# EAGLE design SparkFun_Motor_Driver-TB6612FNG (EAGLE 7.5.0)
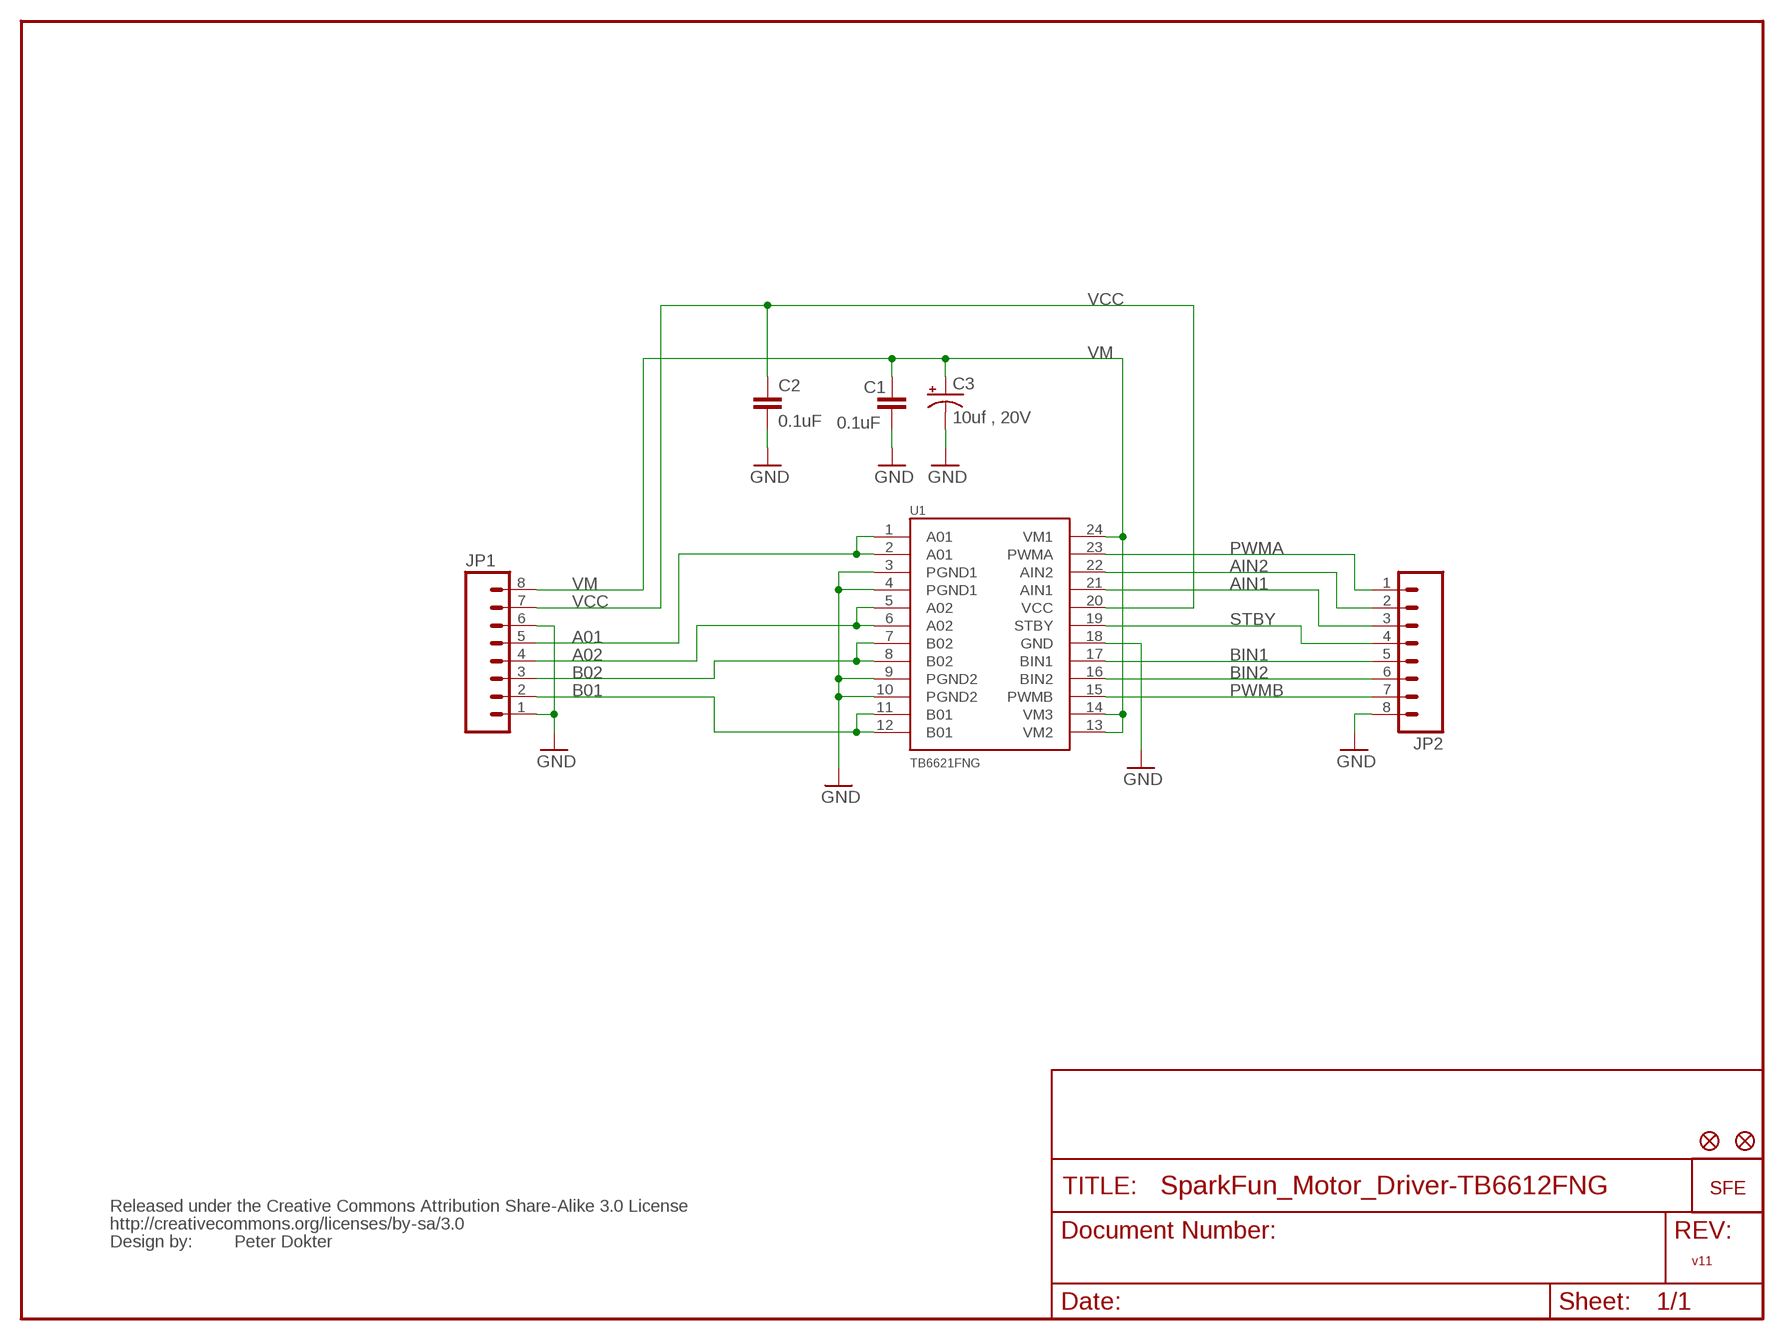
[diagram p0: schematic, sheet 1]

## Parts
C1  0.1uF  CAP0402-CAP  [0402-CAP]
C2  0.1uF  CAP0402-CAP  [0402-CAP]
C3  10uf , 20V  CAP_POL3528  [EIA3528]
JP1  M08LONGPADS  [1X08_LONGPADS]
JP2  M08LONGPADS  [1X08_LONGPADS]
JP4  LOGO-SFESK  [SFE-LOGO-FLAME]
JP5  FIDUCIAL1X2  [FIDUCIAL-1X2]
JP6  FIDUCIAL1X2  [FIDUCIAL-1X2]
U1  TB6621FNG  [SSOP24]
U$1  CREATIVE_COMMONS  [CREATIVE_COMMONS]

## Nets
A01: JP1.5 U1.1(A01) U1.2(A01)
A02: JP1.4 U1.5(A02) U1.6(A02)
AIN1: JP2.3 U1.21(AIN1)
AIN2: JP2.2 U1.22(AIN2)
B01: JP1.2 U1.11(B01) U1.12(B01)
B02: JP1.3 U1.7(B02) U1.8(B02)
BIN1: JP2.5 U1.17(BIN1)
BIN2: JP2.6 U1.16(BIN2)
GND: C1.2 C2.2 C3.C(-) JP1.1 JP1.6 JP2.8 U1.3(PGND1) U1.4(PGND1) U1.9(PGND2) U1.10(PGND2) U1.18(GND)
PWMA: JP2.1 U1.23(PWMA)
PWMB: JP2.7 U1.15(PWMB)
STBY: JP2.4 U1.19(STBY)
VCC: C2.1 JP1.7 U1.20(VCC)
VM: C1.1 C3.A(+) JP1.8 U1.13(VM2) U1.14(VM3) U1.24(VM1)

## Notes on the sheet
- Peter Dokter
- v11

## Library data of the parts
C1 C2 = SparkFun:CAP: Capacitor
C3 = SparkFun:CAP_POL: Capacitor Polarized
JP1 JP2 = SparkFun:M08: Header 8 Standard 8-pin 0.1" header. Use with straight break away headers (SKU : PRT-00116), right angle break away headers (PRT-00553), swiss pins (PRT-00743), machine pins (PRT-00117), and female headers (PRT-00115).
JP4 = SparkFun:LOGO-SFE: Spark Fun Electronics PCB Logo
JP5 JP6 = SparkFun:FIDUCIAL: Fiducial Alignment Points
U1 = SparkFun:TB6621FNG: Toshiba 1A motor driver
U$1 = SparkFun:CREATIVE_COMMONS

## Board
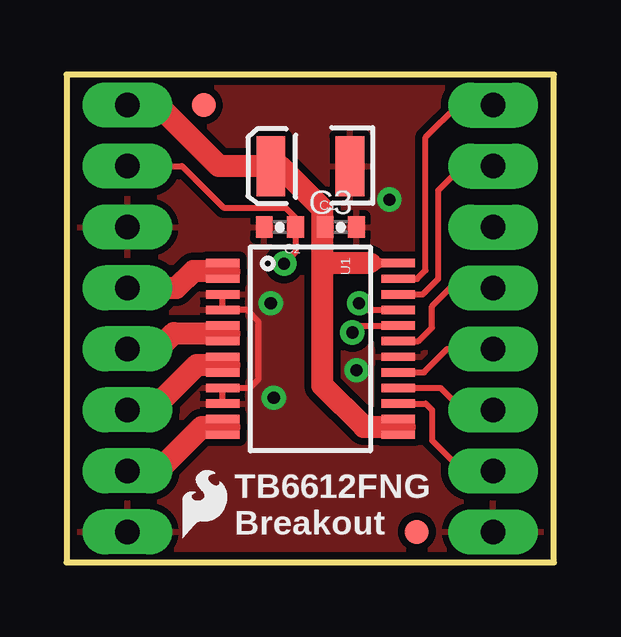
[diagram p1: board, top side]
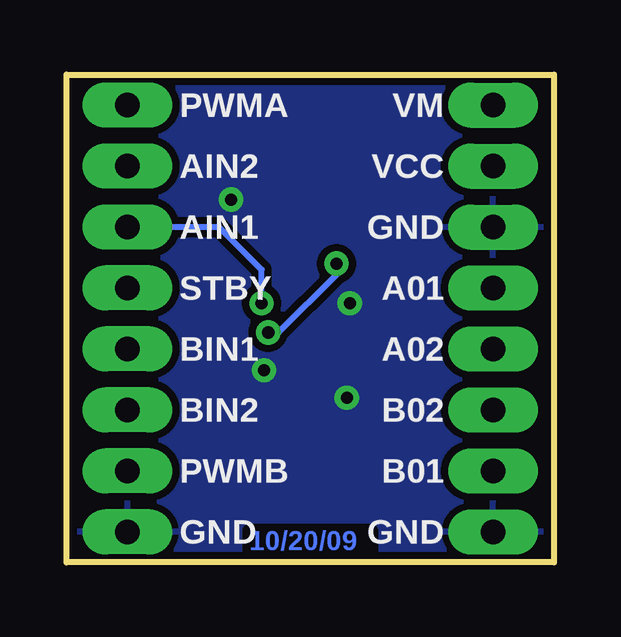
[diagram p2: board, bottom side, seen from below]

Size 20.32 x 20.32 mm. Coordinates in mm from the lower left corner, seen from the top.
Outline: 0,0 20.32,0 20.32,20.32 0,20.32 0,0
Copper layers (1*16): Top 0.035mm / dielectric 1.5mm / Bottom 0.035mm
Design rules "SparkFun": minimum track width 8mil, minimum drill 20mil, track to track 8mil, track to pad 8mil, pad to pad 8mil, via to via 8mil, smd to smd 8mil, copper to edge 9mil, drill to drill 8mil, minimum pad ring 12mil, minimum via ring 10mil, stop-mask expansion 4mil, vias tented up to drill 20mil, thermal gap 10mil

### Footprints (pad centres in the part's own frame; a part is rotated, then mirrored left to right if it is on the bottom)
0402-CAP = smd 0.7 x 0.9: 1 -0.65,0; 2 0.65,0
EIA3528 = smd 1.2 x 2.5: A 1.65,0; C -1.65,0
1X08_LONGPADS = drill 1.016 pad 1.88 long: 1 0,0; 2 2.54,0; 3 5.08,0; 4 7.62,0; 5 10.16,0; 6 12.7,0; 7 15.24,0; 8 17.78,0
FIDUCIAL-1X2 = smd 1 x 1: 1 0,0
SSOP24 = smd 0.348 x 1.397: 1 -3.575,-3.656; 2 -2.925,-3.656; 3 -2.275,-3.656; 4 -1.625,-3.656; 5 -0.975,-3.656; 6 -0.325,-3.656; 7 0.325,-3.656; 8 0.975,-3.656; 9 1.625,-3.656; 10 2.275,-3.656; 11 2.925,-3.656; 12 3.575,-3.656; 13 3.575,3.656; 14 2.925,3.656; 15 2.275,3.656; 16 1.625,3.656; 17 0.975,3.656; 18 0.325,3.656; 19 -0.325,3.656; 20 -0.975,3.656; 21 -1.625,3.656; 22 -2.275,3.656; 23 -2.925,3.656; 24 -3.575,3.656

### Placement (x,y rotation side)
C1  11.43,13.97 0 top
C2  8.89,13.97 180 top
C3  10.16,16.51 180 top
JP1  2.54,1.27 90 top
JP2  17.78,19.05 270 top
JP4  4.83,1.02 0 top
JP5  14.61,1.27 0 top
JP6  5.71,19.05 0 top
U1  10.16,8.89 270 top
U$1  not placed on the board

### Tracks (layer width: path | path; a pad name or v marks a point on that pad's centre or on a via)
A01
  Top 0.254: U1.1 6.5,12.29 6.35,12.14 6.5,11.99 U1.2
  Top 0.914: 6.78,12.12 6.76,12.14 6.35,12.14 5.28,12.14 4.57,11.43 JP1.5
A02
  Top 0.254: U1.5 6.5,9.7 6.35,9.55 6.5,9.4 U1.6
  Top 0.914: 6.78,9.53 6.76,9.55 6.35,9.55 4.47,9.55 3.81,8.89 JP1.4
AIN1  (via drill 0.51)
  Top 0.254: U1.21 12.47,10.52 v12.19,10.79
  Bottom 0.254: v12.19,10.79 12.19,12.19 13.97,13.97 JP2.3
AIN2
  Top 0.254: U1.22 14.85,11.16 15.49,11.81 15.49,15.49 16.51,16.51 JP2.2
B01
  Top 0.254: U1.12 6.5,5.49 6.35,5.64 6.5,5.79 U1.11
  Top 0.914: 6.78,5.64 6.35,5.64 5.64,5.64 3.81,3.81 JP1.2
B02
  Top 0.254: U1.8 6.5,8.08 6.35,8.23 6.5,8.38 U1.7
  Top 0.914: 6.78,8.23 6.35,8.23 5.44,8.23 3.56,6.35 JP1.3
BIN1
  Top 0.254: U1.17 14.9,7.92 15.88,8.89 JP2.5
BIN2
  Top 0.254: U1.16 15.6,7.26 16.51,6.35 JP2.6
GND  (via drill 0.51)
  Top 0.254: U1.10 U1.9 7.65,7.26 8,7.62 8,10.03 7.52,10.52 U1.4 U1.3
  other vias: 12.09,8 13.46,15.11 8.51,10.79 8.64,6.86
  pour Top (isolate 0.305): 0,0 20.32,0 20.32,20.32 0,20.32
  pour Bottom (isolate 0.305): 0,0 20.32,0 20.32,20.32 0,20.32
PWMA
  Top 0.254: U1.23 14.61,11.81 14.96,12.17 14.96,17.7 16.31,19.05 JP2.1
PWMB
  Top 0.254: U1.15 14.97,6.62 15.24,6.35 15.24,5.08 16.51,3.81 JP2.7
STBY
  Top 0.254: U1.19 14.68,9.21 15.24,9.78 15.24,10.67 16,11.43 JP2.4
VCC  (via drill 0.51)
  Top 0.254: JP1.7 4.81,16.51 6.54,14.78 9.12,14.78 9.54,14.36 C2.1 9.54,12.92 v9.07,12.45 | U1.20 12.2,9.87 v11.91,9.58
  Bottom 0.254: v9.07,12.45 9.07,11.99 11.48,9.58 v11.91,9.58
VM
  Top 0.254: 10.67,13.97 C1.1 | U1.14 13.82,5.79 13.97,5.64 13.82,5.49 U1.13
  Top 0.356: U1.24 13.06,12.46 13.06,12.47
  Top 0.406: 13.06,12.46 12.83,12.46 12.95,12.47
  Top 0.61: 12.83,12.46 12.58,12.46 12.7,12.47
  Top 0.813: 12.57,12.47 12.7,12.47
  Top 0.914: 10.67,12.7 10.67,7.37 12.39,5.64 13.97,5.64 14.1,5.64 | 10.67,12.7 10.67,13.97 10.67,14.73 8.89,16.51 C3.A 6.35,16.51 3.81,19.05 JP1.8 | 12.57,12.47 10.9,12.47 10.67,12.7

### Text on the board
Bottom: 10/20/09
tPlace: TB6612FNG | Breakout
bPlace: VM | PWMA | VCC | AIN2 | GND | AIN1 | A01 | STBY | A02 | BIN1 | B02 | BIN2 | B01 | PWMB | GND | GND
